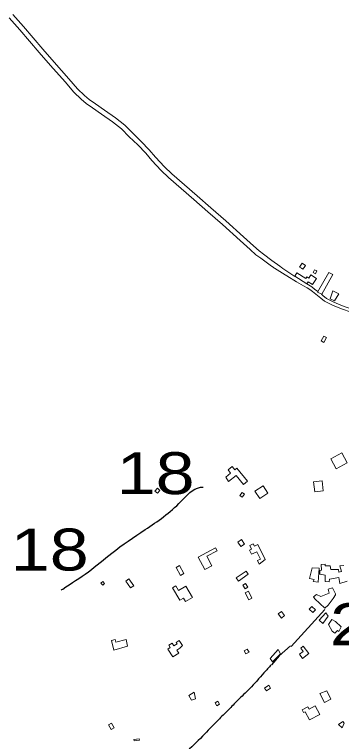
# Model space of a CAD drawing. Extents: x 476989 to 498418, y 4381813 to 4416555.
# Drawn here: x 485650 to 486040, y 4385880 to 4386746 of the extents above; entities that cross this region are included whole.
import ezdxf
from ezdxf.enums import TextEntityAlignment as Align

# ---------------------------------------------------------------- set-up
doc = ezdxf.new("R2010")
doc.units = 0
doc.header["$LTSCALE"] = 20
for name, color, linetype, lineweight in [('13', 7, 'Continuous', 13), ('36', 7, 'Continuous', 13), ('47', 7, 'Continuous', 13), ('6', 7, 'Continuous', 25)]:
    doc.layers.add(name, color=color, linetype=linetype, lineweight=lineweight)

msp = doc.modelspace()

# ---------------------------------------------------------------- linework, layer by layer
at = {"layer": '36'}
for p, q in [((485958.73, 4386444.52), (485959.23, 4386444.17)), ((485959.23, 4386444.17), (485960.09, 4386443.64)), ((485968.47, 4386444.51), (485969.59, 4386443.62)), ((485969.59, 4386443.62), (485969.89, 4386443.38))]:
    msp.add_line(p, q, dxfattribs=at)
for points in [[(485643.81, 4386741.94), (485656.59, 4386727.64), (485679.63, 4386700.74), (485693.05, 4386685.1), (485710.33, 4386665.49), (485720.86, 4386653.36), (485729.47, 4386645.11), (485735.56, 4386640.04), (485743.18, 4386634.7), (485753.88, 4386627.12), (485766.9, 4386618), (485777.81, 4386609.54), (485786.93, 4386600.29), (485797.01, 4386590.61), (485806.5, 4386580.76), (485813.89, 4386571.86), (485824.94, 4386560.19), (485833.78, 4386551.77), (485848.96, 4386538.58), (485864.01, 4386525.31), (485880.46, 4386510.97), (485898.1, 4386495.78), (485919.15, 4386476.56), (485931.15, 4386466.11), (485937.93, 4386459.74), (485943.93, 4386455.44), (485954.79, 4386447.35), (485958.73, 4386444.52)], [(485648.17, 4386745.82), (485660.98, 4386731.48), (485684.06, 4386704.54), (485697.45, 4386688.93), (485714.72, 4386669.33), (485725.09, 4386657.39), (485733.36, 4386649.47), (485739.11, 4386644.68), (485746.54, 4386639.47), (485757.24, 4386631.89), (485770.36, 4386622.7), (485781.69, 4386613.91), (485791.03, 4386604.44), (485801.13, 4386594.74), (485810.85, 4386584.65), (485818.25, 4386575.74), (485829.07, 4386564.32), (485837.71, 4386556.08), (485852.8, 4386542.97), (485867.86, 4386529.7), (485884.28, 4386515.38), (485901.98, 4386500.14), (485923.03, 4386480.92), (485935.07, 4386470.44), (485941.64, 4386464.26), (485947.14, 4386460.32), (485956.97, 4386452.87), (485966.63, 4386445.97), (485968.47, 4386444.51)], [(485960.09, 4386443.64), (485972.91, 4386435.65), (485974.99, 4386434.48)], [(485969.89, 4386443.38), (485974.94, 4386439.93), (485984.36, 4386433.94)], [(485974.99, 4386434.48), (485986.32, 4386427.31), (485994.65, 4386422.54), (485998.97, 4386420.3), (486002.25, 4386418.45), (486005.36, 4386415.71), (486009.59, 4386412.64), (486015.46, 4386408.13), (486019.91, 4386404.47), (486029.22, 4386399.61), (486040.03, 4386395.1), (486051.72, 4386391.11)], [(485998.78, 4386424.94), (486000.81, 4386423.66), (486004.47, 4386421.63), (486007.76, 4386418.78), (486011.73, 4386415.89)], [(486053.43, 4386394.57), (486041.36, 4386398.68), (486030.81, 4386403.08), (486022.01, 4386407.71), (486017.89, 4386411.18), (486016, 4386412.63)]]:
    msp.add_lwpolyline(points, dxfattribs=at)
at = {"layer": '47'}
for p, q in [((485990.9, 4386444.46), (485992.28, 4386443.57)), ((485994.78, 4386443.57), (485995.35, 4386444.45))]:
    msp.add_line(p, q, dxfattribs=at)
for points in [[(485993.01, 4386449.5), (485990.09, 4386444.99), (485990.9, 4386444.46)], [(485995.35, 4386444.45), (485996.96, 4386446.94), (485993.01, 4386449.5)], [(485992.28, 4386443.57), (485994.04, 4386442.43), (485994.78, 4386443.57)], [(486046.72, 4386070.77), (486038.05, 4386067.97), (486036.65, 4386075.12), (486025.75, 4386073.18), (486025.33, 4386070.11), (486020.53, 4386070.25), (486020.72, 4386073.32), (486020.54, 4386076.25), (486020.41, 4386078.05), (486014.05, 4386079.05), (486014.19, 4386083.47), (486016.15, 4386083.97), (486015.87, 4386090.88), (486020.53, 4386091.18), (486020.42, 4386089.16), (486026.57, 4386088.92), (486027.11, 4386084.56), (486036.41, 4386084.65), (486036.74, 4386081.42), (486040.06, 4386082.35), (486037.98, 4386088.91), (486042.79, 4386089.59)]]:
    msp.add_lwpolyline(points, dxfattribs=at)
for points in [[(485984.24, 4386434.17), (485998.74, 4386424.88), (486000.25, 4386427.24), (486005.23, 4386424.05), (486010.03, 4386431.55), (486003.62, 4386435.64), (486001.24, 4386431.91), (485998.8, 4386433.45), (485997.55, 4386431.47), (485986.89, 4386438.17)], [(486007.84, 4386441.78), (486006.17, 4386438.43), (486008.97, 4386437.04), (486010.64, 4386440.39)], [(486011.2, 4386414.95), (486025.05, 4386438.61), (486029.67, 4386436.29), (486016.57, 4386412.69)], [(486036.76, 4386412.93), (486031.69, 4386404.67), (486026.63, 4386407.3), (486029.76, 4386416.71)], [(486018.93, 4386362.69), (486015.77, 4386357.05), (486018.83, 4386355.33), (486021.99, 4386360.97)], [(486040.43, 4386223.64), (486027.16, 4386216.6), (486033.48, 4386204.68), (486046.75, 4386211.72)], [(485905.4, 4386189.48), (485914.36, 4386196.78), (485923.06, 4386186.09), (485927.81, 4386189.97), (485915.26, 4386205.32), (485912.85, 4386203.36), (485909.58, 4386207.37), (485904.67, 4386203.37), (485907.77, 4386199.55), (485902.01, 4386194.88)], [(486016.77, 4386190.51), (486018.29, 4386178.58), (486008.1, 4386177.28), (486006.58, 4386189.21)], [(485820.5, 4386181.47), (485817.58, 4386178.17), (485820.56, 4386175.54), (485823.48, 4386178.84)], [(485946.45, 4386184.24), (485936.81, 4386177.9), (485942.48, 4386169.29), (485952.12, 4386175.63)], [(485921.43, 4386176.57), (485918.89, 4386172.89), (485921.72, 4386170.94), (485924.26, 4386174.62)], [(485916.3, 4386117.37), (485919.95, 4386111.96), (485924.45, 4386115), (485920.8, 4386120.41)], [(485876.89, 4386084.84), (485869.15, 4386099.58), (485889.8, 4386110.43), (485891.63, 4386106.92), (485879.31, 4386100.5), (485885.28, 4386089.02)], [(485948.87, 4386096.56), (485940.19, 4386114.32), (485936.24, 4386112.4), (485934.85, 4386115.25), (485930.52, 4386113.14), (485932.58, 4386108.89), (485930.18, 4386107.74), (485932.51, 4386102.87), (485938.97, 4386105.96), (485943.28, 4386096.92), (485939.83, 4386095.3), (485941.71, 4386091.28)], [(485842.71, 4386086.98), (485848, 4386077.72), (485852.14, 4386080.09), (485846.85, 4386089.35)], [(485914.56, 4386074.62), (485926.22, 4386082.81), (485928.74, 4386079.22), (485917.08, 4386071.03)], [(486013.4, 4386086.18), (486012.34, 4386069.69), (486006.34, 4386070.3), (486007.28, 4386072.69), (486001.97, 4386073.89), (486004.85, 4386086.68)], [(485782.75, 4386070.96), (485788.58, 4386062.79), (485792.27, 4386065.42), (485786.44, 4386073.59)], [(485753, 4386068.46), (485755.34, 4386070.6), (485757.57, 4386068.17), (485755.23, 4386066.03)], [(485862.23, 4386051.43), (485854.25, 4386064.91), (485845.73, 4386059.87), (485842.49, 4386065.32), (485838.57, 4386062.99), (485847.33, 4386048.23), (485851.46, 4386050.69), (485853.95, 4386046.5)], [(485922.4, 4386066.1), (485925.03, 4386061.71), (485928.21, 4386063.62), (485925.58, 4386068.01)], [(485928.97, 4386058.73), (485933.14, 4386050.42), (485929.35, 4386048.52), (485925.18, 4386056.83)], [(486020.07, 4386038.59), (486008.15, 4386049.72), (486006.53, 4386052.07), (486010.33, 4386054.94), (486015.54, 4386052.46), (486025.21, 4386056.6), (486024.23, 4386061.42), (486029.2, 4386063), (486032.85, 4386055.89), (486032.91, 4386054.69), (486029.92, 4386050.31), (486024.03, 4386042.21)], [(486008.87, 4386036.73), (486005.96, 4386033.46), (486001.6, 4386037.35), (486004.51, 4386040.62)], [(485964.67, 4386031.73), (485968.36, 4386026.94), (485972, 4386029.75), (485968.31, 4386034.54)], [(486024.29, 4386029.23), (486017.56, 4386020.39), (486013.19, 4386024.28), (486021.27, 4386033.25)], [(486039.64, 4386016.4), (486032.75, 4386022.95), (486028.51, 4386025.04), (486024.6, 4386019.17), (486028.76, 4386011.3), (486032.25, 4386009), (486035.07, 4386012.04), (486036.79, 4386011.04)], [(485784.87, 4385993.49), (485768.67, 4385988.77), (485765.92, 4386000.29), (485770.05, 4386001.29), (485770.75, 4385998.36), (485783.32, 4386001.39)], [(485847.11, 4385991.02), (485843.55, 4385988.82), (485845.93, 4385984.95), (485838.8, 4385980.57), (485833, 4385989.99), (485835.82, 4385991.73), (485834.02, 4385994.63), (485837.98, 4385997.09), (485840.12, 4385993.64), (485844.16, 4385996.15), (485843.05, 4385997.92), (485846.58, 4386000.14), (485850.26, 4385994.27)], [(485927.68, 4385990.02), (485929.81, 4385986.26), (485926.02, 4385984.11), (485923.89, 4385987.87)], [(485957.78, 4385974.73), (485967.3, 4385984.35), (485964.37, 4385989.34), (485954.84, 4385978.75)], [(485993.33, 4385978.8), (486000.92, 4385984.54), (485994.33, 4385993.24), (485991.34, 4385990.99), (485994.22, 4385987.15), (485990.1, 4385984.07)], [(485948.25, 4385943.57), (485953.22, 4385946.83), (485955.38, 4385943.55), (485950.41, 4385940.29)], [(485861.23, 4385928.92), (485857.93, 4385934.52), (485864.29, 4385938.63), (485865.76, 4385930.65)], [(486022.34, 4385940.26), (486027.38, 4385930.21), (486019.57, 4385926.31), (486014.29, 4385936.87)], [(485892.73, 4385927.86), (485894.72, 4385924.36), (485891.3, 4385922.41), (485889.31, 4385925.91)], [(486001.74, 4385905.82), (485996.55, 4385915.34), (485994.89, 4385914.44), (485993.22, 4385917.49), (485999.91, 4385921.16), (486001.4, 4385918.43), (486008.48, 4385922.31), (486014.01, 4385912.2)], [(485762.06, 4385899.5), (485765.2, 4385894.06), (485768.99, 4385896.25), (485765.85, 4385901.69)], [(486040.62, 4385896.25), (486043.32, 4385901.69), (486041.48, 4385903.59), (486036.32, 4385900.14)], [(485798.94, 4385881.34), (485792.79, 4385880.56), (485792.58, 4385882.18), (485798.73, 4385882.96)]]:
    msp.add_lwpolyline(points, close=True, dxfattribs=at)
at = {"layer": '6'}
msp.add_line((485979.85, 4385992.89), (486019.99, 4386036.92), dxfattribs=at)
msp.add_lwpolyline([(485979.18, 4385993.65), (485965.62, 4385981.93), (485956.45, 4385971.26)], dxfattribs=at)
for points in [[(485705.81, 4386060.25), (485707.58, 4386061.46), (485738.19, 4386081.95), (485766.12, 4386104.21), (485805.91, 4386132.23), (485848.56, 4386165.68), (485871.76, 4386182.68), (485874.39, 4386182.72), (485874.99, 4386182.56)], [(485956.23, 4385971.26), (485947.54, 4385961.52), (485930.31, 4385942.56), (485916.08, 4385928.8), (485905.26, 4385917.55), (485892.78, 4385905.28), (485874.27, 4385886.03), (485833.81, 4385845.65), (485813.14, 4385823.32), (485781.72, 4385801.83), (485774.07, 4385789.96), (485761.33, 4385781.76), (485746.04, 4385772.43)]]:
    msp.add_spline(points, degree=3, dxfattribs=at)

# ---------------------------------------------------------------- texts
at = {"layer": '13', "width": 1.25}
for s, p in [('18', (485818.36, 4386174.5)), ('18', (485692.09, 4386083.49)), ('21', (486072.73, 4385994.53))]:
    msp.add_text(s, height=50, dxfattribs=at).set_placement(p, align=Align.CENTER)

doc.saveas('drawing.dxf')
